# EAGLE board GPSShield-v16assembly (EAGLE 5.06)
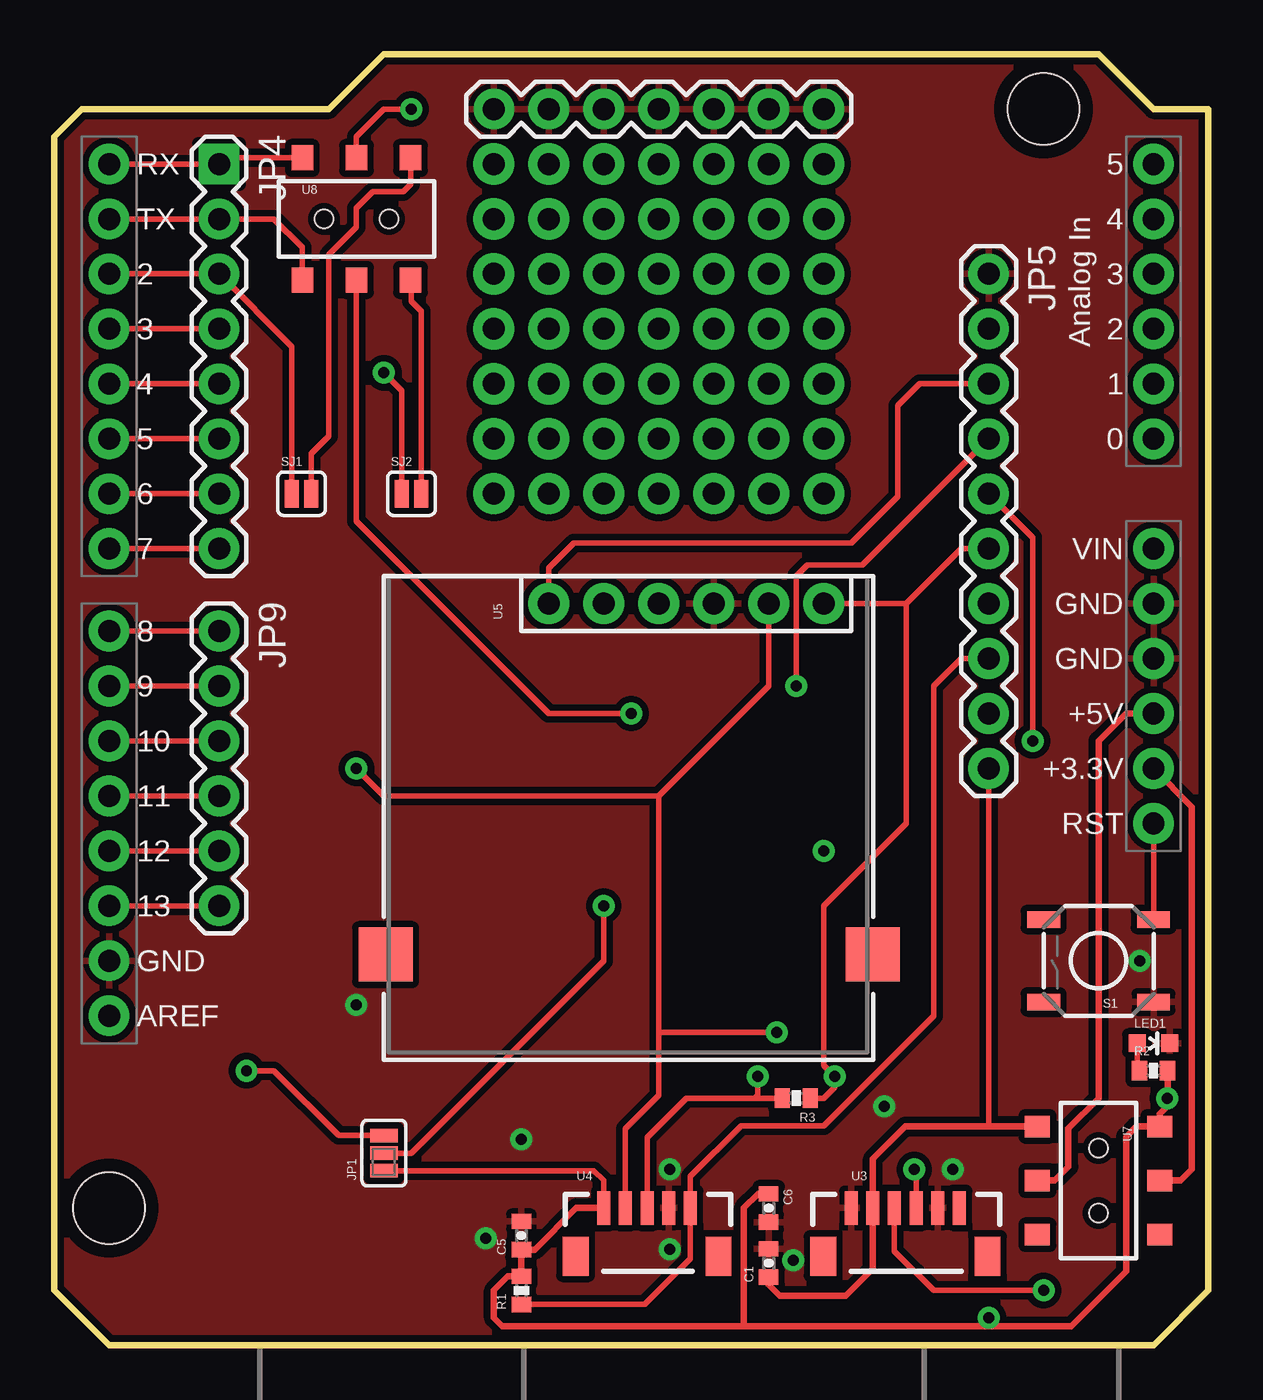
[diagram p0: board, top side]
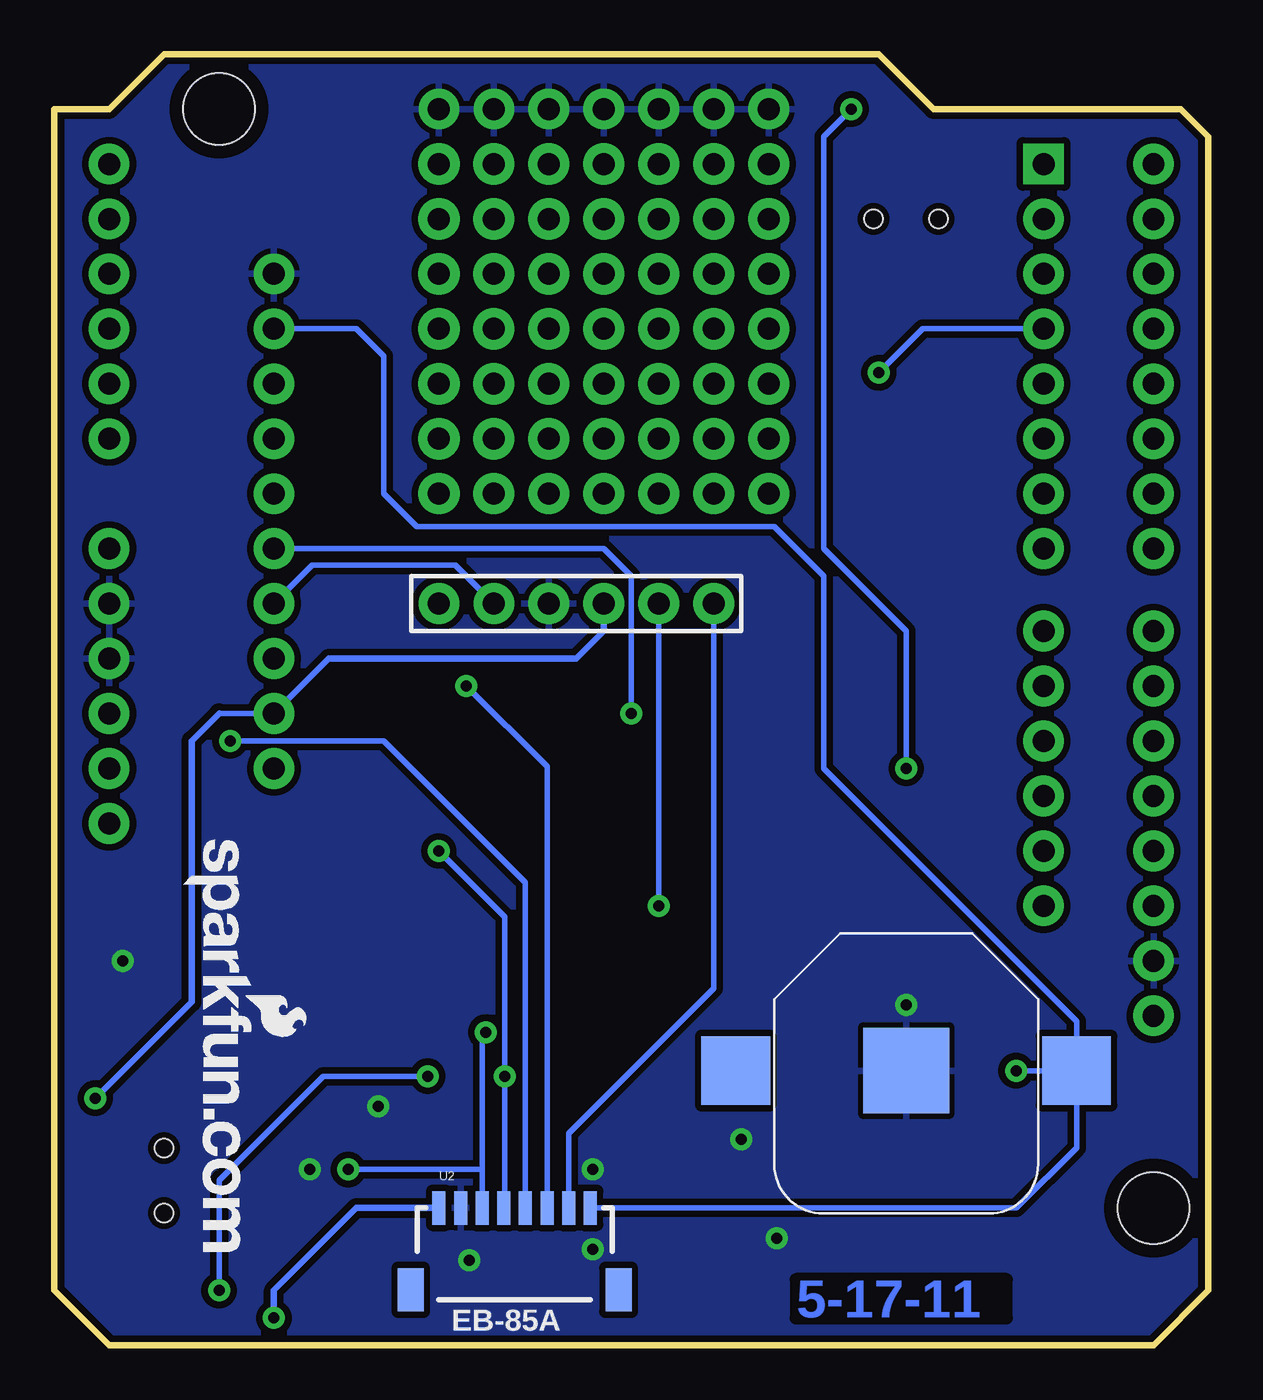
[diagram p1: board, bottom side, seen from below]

Size 53.34 x 59.69 mm. Coordinates in mm from the lower left corner, seen from the top.
Outline: 2.54,0 0,2.54 0,55.88 1.27,57.15 12.7,57.15 15.24,59.69 48.26,59.69 50.8,57.15 53.34,57.15 53.34,2.54 50.8,0 2.54,0
Copper layers (1*16): Top 0.035mm / dielectric 1.5mm / Bottom 0.035mm
Design rules "SparkFun": minimum track width 8mil, minimum drill 20mil, track to track 8mil, track to pad 8mil, pad to pad 8mil, via to via 8mil, smd to smd 8mil, copper to edge 8mil, drill to drill 8mil, minimum pad ring 12mil, minimum via ring 10mil, stop-mask expansion 4mil, vias tented up to drill 20mil, thermal gap 10mil

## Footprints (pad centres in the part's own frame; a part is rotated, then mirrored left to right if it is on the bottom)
BATTCON_12MM = smd 3.962 x 3.962: GND 0,0 | smd 3.175 x 3.175: PWR@1 -7.874,0; PWR@2 7.874,0
0402-CAP = smd 0.7 x 0.9: 1 -0.65,0; 2 0.65,0
SJ_3_PASTE1&2 = smd 0.635 x 1.27: 1 -0.813,0; 2 0,0; 3 0.813,0
1X08 = drill 1.016 pad 1.88 square: 1 0,0 | drill 1.016 pad 1.88 round: 2 2.54,0; 3 5.08,0; 4 7.62,0; 5 10.16,0; 6 12.7,0; 7 15.24,0; 8 17.78,0
1X10 = drill 1.016 pad 1.88 round: 1 0,0; 2 2.54,0; 3 5.08,0; 4 7.62,0; 5 10.16,0; 6 12.7,0; 7 15.24,0; 8 17.78,0; 9 20.32,0; 10 22.86,0
1X07 = drill 1.016 pad 1.88 round: 1 0,0; 2 2.54,0; 3 5.08,0; 4 7.62,0; 5 10.16,0; 6 12.7,0; 7 15.24,0
1X06 = drill 1.016 pad 1.88 round: 1 0,0; 2 2.54,0; 3 5.08,0; 4 7.62,0; 5 10.16,0; 6 12.7,0
LED-0603 = smd 0.8 x 0.8: A 0,-0.75; C 0,0.75
0402-RES = smd 0.7 x 0.9: 1 -0.65,0; 2 0.65,0
TACTILE_SWITCH_SMD = smd 1.524 x 0.762: 1 -2.54,1.905; 2 2.54,1.905; 3 -2.54,-1.905; 4 2.54,-1.905
SJ_2S = smd 0.635 x 1.27: 1 -0.45,0; 2 0.45,0
DUEMILANOVE_SHIELD = drill 1.016 pad 1.88 round: 3.3V 50.8,26.67; 5V 50.8,29.21; A0 50.8,41.91; A1 50.8,44.45; A2 50.8,46.99; A3 50.8,49.53; A4 50.8,52.07; A5 50.8,54.61; AREF 2.54,15.24; D2 2.54,49.53; D3 2.54,46.99; D4 2.54,44.45; D5 2.54,41.91; D6 2.54,39.37; D7 2.54,36.83; D8 2.54,33.02; D9 2.54,30.48; D10 2.54,27.94; D11 2.54,25.4; D12 2.54,22.86; D13 2.54,20.32; GND@0 50.8,31.75; GND@1 50.8,34.29; GND@2 2.54,17.78; RES 50.8,24.13; RX 2.54,54.61; TX 2.54,52.07; VIN 50.8,36.83 | hole 3.302: 45.72,57.15; 2.54,6.35
EB-85A = smd 0.6 x 1.55: 1 0,0; 2 1,0; 3 2,0; 4 3,0; 5 4,0; 6 5,0; 7 6,0; 8 7,0 | smd 1.2 x 2: P$1 -1.3,-3.775; P$2 8.3,-3.775
EM406 = smd 0.6 x 1.55: 1 0,0; 2 1,0; 3 2,0; 4 3,0; 5 4,0; 6 5,0 | smd 1.2 x 1.8: P$1 -1.3,-2.225; P$2 6.3,-2.225
EM408_CON = smd 0.6 x 1.55: 1 4,0; 2 3,0; 3 2,0; 4 1,0; 5 0,0 | smd 1.2 x 1.8: P$1 -1.3,-2.225; P$2 5.3,-2.225
SUP500F = drill 1.016 pad 1.88 round: 1 0,15.24; 2 0,12.7; 3 0,10.16; 4 0,7.62; 5 0,5.08; 6 0,2.54 | smd 2.5 x 2.5: NC@0 16.22,-5; NC@1 16.22,17.51
AYZ0202 = smd 1 x 1.15: 1 -2.5,2.825; 2 0,2.825; 3 2.5,2.825; 4 -2.5,-2.825; 5 0,-2.825; 6 2.5,-2.825 | hole 0.85: 1.5,0; -1.5,0

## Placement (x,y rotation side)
BAT1  DNP_12mm  [BATTCON_12MM]  13.97,12.7 180 bottom
C1  0.1uF  [0402-CAP]  33.02,3.81 90 top
C5  0.1uF  [0402-CAP]  21.59,5.08 90 top
C6  0.1uF  [0402-CAP]  33.02,6.35 270 top
JP1  JUMPER-31-2  [SJ_3_PASTE1&2]  15.24,8.89 90 top
JP3  LOGO-SFENEW  [SFE-NEW-WEBLOGO]  47.37,23.37 270 bottom
JP4  [1X08]  7.62,54.61 270 top
JP5  M10"  [1X10]  43.18,49.53 270 top
JP6  GND  [1X07]  20.32,57.15 0 top
JP9  [1X06]  7.62,33.02 270 top
LED1  Red  [LED-0603]  50.8,13.97 270 top
R1  100k  [0402-RES]  21.59,2.54 90 top
R2  330  [0402-RES]  50.8,12.7 0 top
R3  10k  [0402-RES]  34.29,11.43 180 top
S1  Reset  [TACTILE_SWITCH_SMD]  48.26,17.78 180 top
SJ1  D_RX  [SJ_2S]  11.43,39.37 0 top
SJ2  D_TX  [SJ_2S]  16.51,39.37 0 top
U1  ARDUINO_SHIELD  [DUEMILANOVE_SHIELD]  0,0 0 top
U2  DNP_EB-85A  [EB-85A]  35.56,6.35 0 bottom
U3  EM406  [EM406]  36.83,6.35 0 top
U4  DNP_EM408  [EM408_CON]  25.4,6.35 0 top
U5  DNP_SUP500F  [SUP500F]  20.32,34.29 270 top
U7  AYZ Switch  [AYZ0202]  48.26,7.62 270 top
U8  AYZ Switch  [AYZ0202]  13.97,52.07 0 top
U$5  EM406_OUTLINE  [EM406_OUTLINE]  15.09,12.28 0 top

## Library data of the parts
BAT1 C1 C5 C6 JP1 JP3-JP6 JP9 LED1 R1-R3 S1 SJ1 SJ2 U1-U5 U7 U8 U$5 = SparkFun

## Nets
3.3V: C5.1 C6.1 JP1.1 JP5.9 R1.2 R2.2 U2.1 U4.5 U5.4 U7.1
3.3VIN: U1.3.3V U7.2
5V: C1.1 JP5.10 U3.2 U7.4
5VIN: U1.5V U7.5
BATT: BAT1.PWR@1 JP1.3 JP5.2 U2.8
D_RX: JP4.3 SJ1.1 U1.D2
D_TX: JP4.4 SJ2.1 U1.D3
EN: JP5.8 R1.1 U4.1
GND: BAT1.GND C1.2 C5.2 C6.2 JP5.1 JP6.1 JP6.2 JP6.3 JP6.4 JP6.5 JP6.6 JP6.7 LED1.C S1.1 U1.GND@0 U1.GND@1 U1.GND@2 U2.2 U3.1 U3.5 U4.2 U5.3
N$1: LED1.A R2.1
N$111: JP4.5 U1.D4
N$112: JP4.6 U1.D5
N$113: JP4.7 U1.D6
N$114: JP4.8 U1.D7
N$115: JP9.1 U1.D8
N$116: JP9.2 U1.D9
N$117: JP9.3 U1.D10
N$118: JP9.4 U1.D11
N$119: JP9.5 U1.D12
N$120: JP9.6 U1.D13
N$121: SJ2.2 U8.6
N$122: SJ1.2 U8.3
PPS: JP5.3 U2.7 U5.6
RES: S1.3 U1.RES
RX: JP5.6 R3.1 U3.3 U5.1 U8.5
RX2: JP5.4 U2.6
RX_LV: R3.2 U2.4 U4.3
TX: JP5.7 U2.3 U3.4 U4.4 U5.2 U8.2
TX2: JP5.5 U2.5
UART_RX: JP4.1 U1.RX U8.1
UART_TX: JP4.2 U1.TX U8.4
VBATT: JP1.2 U5.5

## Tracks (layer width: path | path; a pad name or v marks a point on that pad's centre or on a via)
3.3V  (via drill 0.51)
  Top 0.254: C6.1 33.01,6.99 | 51.45,11.41 v51.44,11.43 51.45,11.45 | U4.5 25.4,7.62 24.94,8.08 JP1.1
  Top 0.305: U4.5 24.13,6.35 22.21,4.43 C5.1 R1.2 20.97,3.19 20.32,2.54 20.32,1.27 20.7,0.89 31.88,0.89 | C6.1 32.53,7 31.88,6.35 31.88,0.89 | 31.88,0.89 43.18,0.89 | 43.18,0.89 46.99,0.89 49.53,3.43 49.53,9.65 50,10.12 U7.1 51.09,10.7 51.45,11.06 51.45,11.41 | 43.18,0.89 v43.18,1.27 | 51.45,11.45 R2.2
  Bottom 0.254: v51.44,11.43 v51.45,11.43 | 45.72,29.21 JP5.9 40.64,31.75
  Bottom 0.305: U5.4 27.94,33.02 29.21,31.75 40.64,31.75 | 45.72,29.21 46.99,27.94 46.99,15.88 v51.44,11.43 | U2.1 39.37,6.35 43.18,2.54 v43.18,1.27
3.3VIN
  Top 0.305: U1.3.3V 52.58,24.89 52.58,8.13 52.07,7.62 U7.2
5V
  Top 0.254: 43.22,10.12 43.18,10.16 | 43.18,10.12 JP5.10
  Top 0.305: 43.22,10.12 U7.4 43.18,10.12 39.33,10.12 37.83,8.62 U3.2 37.83,3.54 36.58,2.29 33.53,2.29 33.02,2.79 C1.1
5VIN
  Top 0.305: U1.5V 49.53,29.21 48.26,27.94 48.26,11.43 46.86,10.03 46.86,8.26 46.23,7.62 U7.5
BATT  (via drill 0.51)
  Top 0.254: JP1.3 13.16,9.7 10.16,12.7 v8.89,12.7
  Bottom 0.254: U2.8 8.89,6.35 6.1,9.14 BAT1.PWR@1 | BAT1.PWR@1 6.1,14.99 7.62,16.51 17.78,26.67 17.78,35.56 20.07,37.85 25.4,37.85 36.58,37.85 38.1,39.37 38.1,45.72 39.37,46.99 JP5.2 | BAT1.PWR@1 v8.89,12.7
D_RX
  Top 0.254: U1.D2 JP4.3 10.98,46.17 10.98,44.9 SJ1.1
D_TX  (via drill 0.51)
  Top 0.254: U1.D3 JP4.4 | SJ2.1 16.06,44.14 v15.24,44.96
  Bottom 0.254: JP4.4 13.21,46.99 v15.24,44.96
EN
  Top 0.254: R1.1 27.29,1.89 29.4,4 U4.1 29.4,7.81 31.75,10.16 35.56,10.16 40.64,15.24 40.64,30.48 41.91,31.75 JP5.8
GND  (via drill 0.51)
  other vias: 21.59,9.53 38.35,11.05 34.16,3.94 50.16,17.78 28.45,4.45 41.53,8.13 28.45,8.13 13.97,15.75 19.94,4.95
  pour Top (isolate 0.305): 0,0 0,59.69 53.34,59.69 53.34,0
  pour Bottom (isolate 0.305): 0,0 0,59.69 53.34,59.69 53.34,0
N$1
  Top 0.254: LED1.A 50.05,12.8 R2.1
N$2  (via drill 1.02 pad 1.91)
  other vias: 22.86,54.61
N$4  (via drill 1.02 pad 1.91)
  other vias: 22.86,39.37
N$6  (via drill 1.02 pad 1.91)
  other vias: 22.86,41.91
N$7  (via drill 1.02 pad 1.91)
  other vias: 22.86,44.45
N$8  (via drill 1.02 pad 1.91)
  other vias: 22.86,46.99
N$9  (via drill 1.02 pad 1.91)
  other vias: 22.86,49.53
N$10  (via drill 1.02 pad 1.91)
  other vias: 22.86,52.07
N$11  (via drill 1.02 pad 1.91)
  other vias: 20.32,39.37
N$13  (via drill 1.02 pad 1.91)
  other vias: 25.4,39.37
N$15  (via drill 1.02 pad 1.91)
  other vias: 27.94,39.37
N$16  (via drill 1.02 pad 1.91)
  other vias: 20.32,41.91
N$17  (via drill 1.02 pad 1.91)
  other vias: 20.32,44.45
N$18  (via drill 1.02 pad 1.91)
  other vias: 20.32,46.99
N$19  (via drill 1.02 pad 1.91)
  other vias: 20.32,49.53
N$20  (via drill 1.02 pad 1.91)
  other vias: 20.32,54.61
N$21  (via drill 1.02 pad 1.91)
  other vias: 20.32,52.07
N$23  (via drill 1.02 pad 1.91)
  other vias: 30.48,39.37
N$25  (via drill 1.02 pad 1.91)
  other vias: 33.02,39.37
N$27  (via drill 1.02 pad 1.91)
  other vias: 35.56,39.37
N$28  (via drill 1.02 pad 1.91)
  other vias: 25.4,41.91
N$29  (via drill 1.02 pad 1.91)
  other vias: 25.4,44.45
N$30  (via drill 1.02 pad 1.91)
  other vias: 25.4,46.99
N$31  (via drill 1.02 pad 1.91)
  other vias: 25.4,49.53
N$32  (via drill 1.02 pad 1.91)
  other vias: 25.4,54.61
N$33  (via drill 1.02 pad 1.91)
  other vias: 25.4,52.07
N$40  (via drill 1.02 pad 1.91)
  other vias: 27.94,41.91
N$41  (via drill 1.02 pad 1.91)
  other vias: 27.94,44.45
N$42  (via drill 1.02 pad 1.91)
  other vias: 27.94,46.99
N$43  (via drill 1.02 pad 1.91)
  other vias: 27.94,49.53
N$44  (via drill 1.02 pad 1.91)
  other vias: 27.94,54.61
N$45  (via drill 1.02 pad 1.91)
  other vias: 27.94,52.07
N$52  (via drill 1.02 pad 1.91)
  other vias: 30.48,41.91
N$53  (via drill 1.02 pad 1.91)
  other vias: 30.48,44.45
N$54  (via drill 1.02 pad 1.91)
  other vias: 30.48,46.99
N$55  (via drill 1.02 pad 1.91)
  other vias: 30.48,49.53
N$56  (via drill 1.02 pad 1.91)
  other vias: 30.48,54.61
N$57  (via drill 1.02 pad 1.91)
  other vias: 30.48,52.07
N$64  (via drill 1.02 pad 1.91)
  other vias: 33.02,41.91
N$65  (via drill 1.02 pad 1.91)
  other vias: 33.02,44.45
N$66  (via drill 1.02 pad 1.91)
  other vias: 33.02,46.99
N$67  (via drill 1.02 pad 1.91)
  other vias: 33.02,49.53
N$68  (via drill 1.02 pad 1.91)
  other vias: 33.02,54.61
N$69  (via drill 1.02 pad 1.91)
  other vias: 33.02,52.07
N$76  (via drill 1.02 pad 1.91)
  other vias: 35.56,41.91
N$77  (via drill 1.02 pad 1.91)
  other vias: 35.56,44.45
N$78  (via drill 1.02 pad 1.91)
  other vias: 35.56,46.99
N$79  (via drill 1.02 pad 1.91)
  other vias: 35.56,49.53
N$80  (via drill 1.02 pad 1.91)
  other vias: 35.56,54.61
N$81  (via drill 1.02 pad 1.91)
  other vias: 35.56,52.07
N$111
  Top 0.254: U1.D4 JP4.5
N$112
  Top 0.254: U1.D5 JP4.6
N$113
  Top 0.254: U1.D6 JP4.7
N$114
  Top 0.254: U1.D7 JP4.8
N$115
  Top 0.254: U1.D8 JP9.1
N$116
  Top 0.254: U1.D9 JP9.2
N$117
  Top 0.254: U1.D10 JP9.3
N$118
  Top 0.254: U1.D11 JP9.4
N$119
  Top 0.254: U1.D12 JP9.5
N$120
  Top 0.254: U1.D13 JP9.6
N$121
  Top 0.254: SJ2.2 16.96,47.81 16.51,48.26 16.51,49.2 U8.6
N$122
  Top 0.254: U8.3 16.47,53.68 16.13,53.34 14.73,53.34 13.97,52.58 13.97,51.69 12.7,50.42 12.7,42.04 11.88,41.22 SJ1.2
PPS
  Top 0.254: U5.6 22.86,35.94 24,37.08 36.83,37.08 38.99,39.24 38.99,43.43 40.01,44.45 JP5.3
  Bottom 0.254: U2.7 29.56,9.81 22.86,16.51 U5.6
RES
  Top 0.254: S1.3 U1.RES
RX  (via drill 0.51)
  Top 0.254: U3.3 38.83,4.35 40.64,2.54 v45.72,2.54 | R3.1 35.56,11.43 36.07,11.94 v36.07,12.45 35.56,12.95 35.56,20.32 39.37,24.13 39.37,34.29 | 39.37,34.29 41.91,36.83 JP5.6 | v26.67,29.21 22.86,29.21 13.97,38.1 U8.5 | 39.37,34.29 U5.1
  Bottom 0.254: v36.07,12.45 40.89,12.45 45.72,7.62 v45.72,2.54 | v26.67,29.21 26.67,35.56 27.94,36.83 JP5.6
RX2  (via drill 0.51)
  Top 0.254: v34.29,30.48 34.29,35.56 34.8,36.07 37.34,36.07 JP5.4
  Bottom 0.254: U2.6 30.56,26.75 v34.29,30.48
RX_LV  (via drill 0.51)
  Top 0.254: U4.3 27.4,9.62 29.21,11.43 32.38,11.43 | 32.38,11.43 R3.2 | v32.51,12.45 32.51,11.56 32.38,11.43
  Bottom 0.254: U2.4 32.51,6.4 v32.51,12.45 32.51,19.81 v35.56,22.86
TX  (via drill 0.51)
  Top 0.254: U3.4 39.83,8.05 v39.75,8.13 | U5.2 33.02,30.48 27.94,25.4 | 27.94,14.48 27.94,11.56 26.4,10.02 U4.4 | 27.94,14.48 27.94,25.4 | 27.94,25.4 15.24,25.4 v13.97,26.67 | 27.94,14.48 v33.4,14.48 | U8.2 13.97,55.88 15.24,57.15 v16.51,57.15
  Bottom 0.254: 33.56,8.13 U2.3 | 33.56,8.13 v39.75,8.13 33.56,8.13 | U5.2 34.8,36.07 41.4,36.07 JP5.7 | 33.56,8.13 33.56,14.32 v33.4,14.48 | v16.51,57.15 17.78,55.88 17.78,36.83 13.97,33.02 v13.97,26.67
TX2  (via drill 0.51)
  Top 0.254: v45.21,27.94 45.21,37.34 JP5.5
  Bottom 0.254: U2.5 31.56,21.4 38.1,27.94 v45.21,27.94
UART_RX
  Top 0.254: U1.RX JP4.1 7.91,54.9 U8.1
UART_TX
  Top 0.254: U1.TX JP4.2 10.16,52.07 11.47,50.76 U8.4
VBATT  (via drill 0.51)
  Top 0.254: v25.4,20.32 25.4,17.78 16.51,8.89 JP1.2
  Bottom 0.254: v25.4,20.32 U5.5

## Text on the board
Bottom: 5-17-11
bPlace: EB-85A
